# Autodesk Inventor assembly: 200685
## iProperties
Created: 2007-12
Part Number: 200685
Document SubType Name: Assembly
Designer: MM
Mass: 762.988 g
Surface Area: 385.242 cm^2
Volume: 97.3962 cm^3
Density: 7.83386 g/cm^3
Description: PIVOT LINK WELDMENT
Component Category: Lower Component
Author: MM
